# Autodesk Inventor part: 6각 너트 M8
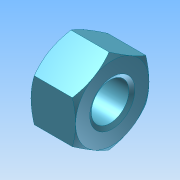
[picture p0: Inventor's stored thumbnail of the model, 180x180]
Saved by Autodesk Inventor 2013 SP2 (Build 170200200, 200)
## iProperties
Created: 2025-07
Part Number: 6각 너트 M8
Material: Generic
Document SubType Name: Modeling
Designer: a
Density: 1 g/cm^3
Author: a
변환 표준: STEP AP214IS
전처리기: Build: 200, Release: 2013 SP2 Update 6 - Date: Thu 07/17/2014
전송 단위: 밀리미터
불확실성: 0.01
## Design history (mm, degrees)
node "6각 너트 M81"
body "Solid1"
node "기준1"
